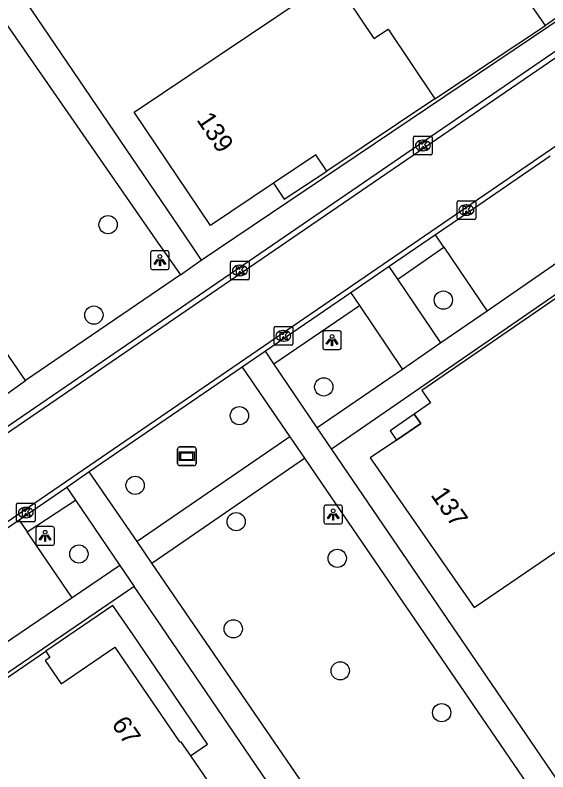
# Model space of a CAD drawing. Extents: x 155275 to 156263, y 382654 to 383635.
# Drawn here: x 155477.14 to 155505.69, y 383303.66 to 383344.2 of the extents above; entities that cross this region are included whole.
import ezdxf

# ---------------------------------------------------------------- set-up
doc = ezdxf.new("R2010")
doc.units = 0
for name, color, linetype in [('IMGEO_Boom', 7, 'Continuous'), ('IMGEO_Kolk', 7, 'Continuous'), ('IMGEO_Lichtpunt', 7, 'Continuous'), ('IMGEO_Muur', 7, 'Continuous'), ('IMGEO_Pand', 7, 'Continuous'), ('IMGEO_Pand_nummerreeks', 7, 'Continuous'), ('IMGEO_Pand_overbouw', 7, 'Continuous'), ('IMGEO_Parkeervlak_open', 7, 'Continuous'), ('IMGEO_Rijbaan_lokaal_open', 7, 'Continuous'), ('IMGEO_Straatnaambord', 7, 'Continuous'), ('IMGEO_Voetpad_open', 7, 'Continuous')]:
    doc.layers.add(name, color=color, linetype=linetype)

msp = doc.modelspace()

# ---------------------------------------------------------------- linework, layer by layer
at = {"layer": 'IMGEO_Boom'}
for centre in [(155482.122, 383332.97), (155500.085, 383328.932), (155481.36, 383328.128), (155493.679, 383324.283), (155489.159, 383322.742), (155483.57, 383319.01), (155488.986, 383317.065), (155480.556, 383315.331), (155494.4, 383315.099), (155488.828, 383311.321), (155494.56, 383309.073), (155499.993, 383306.834)]:
    msp.add_circle(centre, 0.489, dxfattribs=at)
at = {"layer": 'IMGEO_Kolk'}
for p, q in [((155498.488, 383336.787), (155498.488, 383337.639)), ((155498.563, 383337.713), (155499.415, 383337.713)), ((155498.976, 383337.493), (155499.001, 383337.493)), ((155499.489, 383337.639), (155499.489, 383336.787)), ((155498.999, 383336.933), (155498.974, 383336.933)), ((155499.415, 383336.713), (155498.563, 383336.713)), ((155500.824, 383333.33), (155500.824, 383334.182)), ((155500.899, 383334.256), (155501.751, 383334.256)), ((155501.825, 383334.182), (155501.825, 383333.33)), ((155501.312, 383334.036), (155501.337, 383334.036)), ((155501.335, 383333.476), (155501.31, 383333.476)), ((155501.751, 383333.256), (155500.899, 383333.256)), ((155488.681, 383330.094), (155488.681, 383330.946)), ((155488.756, 383331.02), (155489.608, 383331.02)), ((155489.682, 383330.946), (155489.682, 383330.094)), ((155489.169, 383330.8), (155489.194, 383330.8)), ((155489.192, 383330.24), (155489.167, 383330.24)), ((155489.608, 383330.02), (155488.756, 383330.02)), ((155491.015, 383326.593), (155491.015, 383327.445)), ((155491.09, 383327.519), (155491.942, 383327.519)), ((155491.503, 383327.299), (155491.528, 383327.299)), ((155492.016, 383327.445), (155492.016, 383326.593)), ((155491.942, 383326.519), (155491.09, 383326.519)), ((155491.526, 383326.739), (155491.501, 383326.739)), ((155477.213, 383317.123), (155477.213, 383317.975)), ((155477.288, 383318.049), (155478.14, 383318.049)), ((155478.214, 383317.975), (155478.214, 383317.123)), ((155477.701, 383317.829), (155477.726, 383317.829)), ((155477.724, 383317.269), (155477.699, 383317.269)), ((155478.14, 383317.049), (155477.288, 383317.049))]:
    msp.add_line(p, q, dxfattribs=at)
for points in [[(155498.488, 383336.787), (155498.488, 383337.639)], [(155498.563, 383337.713), (155499.415, 383337.713)], [(155498.809, 383337.413), (155498.932, 383337.413), (155498.932, 383337.262), (155499.062, 383337.413), (155499.226, 383337.413), (155499.08, 383337.262), (155499.233, 383337.013), (155499.081, 383337.013), (155498.996, 383337.177), (155498.932, 383337.11), (155498.932, 383337.013), (155498.809, 383337.013), (155498.809, 383337.413)], [(155499.489, 383337.639), (155499.489, 383336.787)], [(155499.415, 383336.713), (155498.563, 383336.713)], [(155500.824, 383333.33), (155500.824, 383334.182)], [(155500.899, 383334.256), (155501.751, 383334.256)], [(155501.825, 383334.182), (155501.825, 383333.33)], [(155501.145, 383333.956), (155501.268, 383333.956), (155501.268, 383333.805), (155501.398, 383333.956), (155501.562, 383333.956), (155501.416, 383333.805), (155501.569, 383333.556), (155501.417, 383333.556), (155501.332, 383333.72), (155501.268, 383333.653), (155501.268, 383333.556), (155501.145, 383333.556), (155501.145, 383333.956)], [(155501.751, 383333.256), (155500.899, 383333.256)], [(155488.681, 383330.094), (155488.681, 383330.946)], [(155488.756, 383331.02), (155489.608, 383331.02)], [(155489.682, 383330.946), (155489.682, 383330.094)], [(155489.002, 383330.72), (155489.125, 383330.72), (155489.125, 383330.569), (155489.255, 383330.72), (155489.419, 383330.72), (155489.273, 383330.569), (155489.426, 383330.32), (155489.274, 383330.32), (155489.189, 383330.484), (155489.125, 383330.417), (155489.125, 383330.32), (155489.002, 383330.32), (155489.002, 383330.72)], [(155489.608, 383330.02), (155488.756, 383330.02)], [(155491.015, 383326.593), (155491.015, 383327.445)], [(155491.09, 383327.519), (155491.942, 383327.519)], [(155491.336, 383327.219), (155491.459, 383327.219), (155491.459, 383327.068), (155491.589, 383327.219), (155491.753, 383327.219), (155491.607, 383327.068), (155491.76, 383326.819), (155491.608, 383326.819), (155491.523, 383326.983), (155491.459, 383326.916), (155491.459, 383326.819), (155491.336, 383326.819), (155491.336, 383327.219)], [(155492.016, 383327.445), (155492.016, 383326.593)], [(155491.942, 383326.519), (155491.09, 383326.519)], [(155477.213, 383317.123), (155477.213, 383317.975)], [(155477.288, 383318.049), (155478.14, 383318.049)], [(155478.214, 383317.975), (155478.214, 383317.123)], [(155477.534, 383317.749), (155477.657, 383317.749), (155477.657, 383317.598), (155477.787, 383317.749), (155477.951, 383317.749), (155477.805, 383317.598), (155477.958, 383317.349), (155477.806, 383317.349), (155477.721, 383317.513), (155477.657, 383317.446), (155477.657, 383317.349), (155477.534, 383317.349), (155477.534, 383317.749)], [(155478.14, 383317.049), (155477.288, 383317.049)]]:
    msp.add_lwpolyline(points, dxfattribs=at)
for centre, start, end in [((155498.565, 383337.637), 91.552, 178.448), ((155498.565, 383337.637), 91.552, 178.448), ((155499.413, 383337.637), 1.552, 88.448), ((155499.413, 383337.637), 1.552, 88.448), ((155498.565, 383336.789), 181.552, 268.448), ((155498.565, 383336.789), 181.552, 268.448), ((155499.413, 383336.789), 271.552, 358.448), ((155499.413, 383336.789), 271.552, 358.448), ((155500.901, 383334.18), 91.552, 178.448), ((155500.901, 383334.18), 91.552, 178.448), ((155501.749, 383334.18), 1.552, 88.448), ((155501.749, 383334.18), 1.552, 88.448), ((155500.901, 383333.332), 181.552, 268.448), ((155500.901, 383333.332), 181.552, 268.448), ((155501.749, 383333.332), 271.552, 358.448), ((155501.749, 383333.332), 271.552, 358.448), ((155488.758, 383330.944), 91.552, 178.448), ((155488.758, 383330.944), 91.552, 178.448), ((155489.606, 383330.944), 1.552, 88.448), ((155489.606, 383330.944), 1.552, 88.448), ((155488.758, 383330.096), 181.552, 268.448), ((155488.758, 383330.096), 181.552, 268.448), ((155489.606, 383330.096), 271.552, 358.448), ((155489.606, 383330.096), 271.552, 358.448), ((155491.092, 383327.443), 91.552, 178.448), ((155491.092, 383327.443), 91.552, 178.448), ((155491.94, 383327.443), 1.552, 88.448), ((155491.94, 383327.443), 1.552, 88.448), ((155491.092, 383326.595), 181.552, 268.448), ((155491.092, 383326.595), 181.552, 268.448), ((155491.94, 383326.595), 271.552, 358.448), ((155491.94, 383326.595), 271.552, 358.448), ((155477.29, 383317.973), 91.552, 178.448), ((155477.29, 383317.973), 91.552, 178.448), ((155478.138, 383317.973), 1.552, 88.448), ((155478.138, 383317.973), 1.552, 88.448), ((155477.29, 383317.125), 181.552, 268.448), ((155477.29, 383317.125), 181.552, 268.448), ((155478.138, 383317.125), 271.552, 358.448), ((155478.138, 383317.125), 271.552, 358.448)]:
    msp.add_arc(centre, 0.0765, start, end, dxfattribs=at)
for centre, major_axis, ratio, start_param, end_param in [((155498.975, 383337.213), (-0.387, 0.002), 0.722429, 4.712389, 7.853982), ((155499, 383337.213), (-0.39, 0.002), 0.717154, 1.570796, 4.712389), ((155501.311, 383333.756), (-0.387, 0.002), 0.722429, 4.712389, 7.853982), ((155501.336, 383333.756), (-0.39, 0.002), 0.717154, 1.570796, 4.712389), ((155489.168, 383330.52), (-0.387, 0.002), 0.722429, 4.712389, 7.853982), ((155489.193, 383330.52), (-0.39, 0.002), 0.717154, 1.570796, 4.712389), ((155491.502, 383327.019), (-0.387, 0.002), 0.722429, 4.712389, 7.853982), ((155491.527, 383327.019), (-0.39, 0.002), 0.717154, 1.570796, 4.712389), ((155477.7, 383317.549), (-0.387, 0.002), 0.722429, 4.712389, 7.853982), ((155477.725, 383317.549), (-0.39, 0.002), 0.717154, 1.570796, 4.712389)]:
    msp.add_ellipse(centre, major_axis=major_axis, ratio=ratio, start_param=start_param, end_param=end_param, dxfattribs=at)
at = {"layer": 'IMGEO_Lichtpunt'}
for p, q in [((155484.398, 383331.469), (155484.398, 383330.662)), ((155484.398, 383331.469), (155484.398, 383330.662)), ((155485.3, 383331.564), (155484.492, 383331.564)), ((155485.3, 383331.564), (155484.492, 383331.564)), ((155485.394, 383330.662), (155485.394, 383331.469)), ((155485.394, 383330.662), (155485.394, 383331.469)), ((155484.492, 383330.568), (155485.3, 383330.568)), ((155484.492, 383330.568), (155485.3, 383330.568)), ((155494.525, 383327.284), (155493.717, 383327.284)), ((155494.525, 383327.284), (155493.717, 383327.284)), ((155493.623, 383327.189), (155493.623, 383326.382)), ((155493.623, 383327.189), (155493.623, 383326.382)), ((155494.619, 383326.382), (155494.619, 383327.189)), ((155494.619, 383326.382), (155494.619, 383327.189)), ((155493.717, 383326.288), (155494.525, 383326.288)), ((155493.717, 383326.288), (155494.525, 383326.288)), ((155494.587, 383317.94), (155493.779, 383317.94)), ((155494.587, 383317.94), (155493.779, 383317.94)), ((155493.685, 383317.845), (155493.685, 383317.038)), ((155493.685, 383317.845), (155493.685, 383317.038)), ((155494.681, 383317.038), (155494.681, 383317.845)), ((155494.681, 383317.038), (155494.681, 383317.845)), ((155478.249, 383316.7), (155478.249, 383315.893)), ((155478.249, 383316.7), (155478.249, 383315.893)), ((155479.151, 383316.795), (155478.343, 383316.795)), ((155479.151, 383316.795), (155478.343, 383316.795)), ((155479.245, 383315.893), (155479.245, 383316.7)), ((155479.245, 383315.893), (155479.245, 383316.7)), ((155493.779, 383316.944), (155494.587, 383316.944)), ((155493.779, 383316.944), (155494.587, 383316.944)), ((155478.343, 383315.799), (155479.151, 383315.799)), ((155478.343, 383315.799), (155479.151, 383315.799))]:
    msp.add_line(p, q, dxfattribs=at)
for points in [[(155484.772, 383331.133), (155484.811, 383331.105), (155484.623, 383330.843), (155484.585, 383330.87), (155484.772, 383331.133)], [(155484.874, 383331.085), (155484.921, 383331.085), (155484.921, 383330.763), (155484.874, 383330.763), (155484.874, 383331.085)], [(155484.984, 383331.105), (155485.022, 383331.132), (155485.209, 383330.87), (155485.17, 383330.842), (155484.984, 383331.105)], [(155493.997, 383326.853), (155494.036, 383326.825), (155493.848, 383326.563), (155493.81, 383326.59), (155493.997, 383326.853)], [(155494.099, 383326.805), (155494.146, 383326.805), (155494.146, 383326.483), (155494.099, 383326.483), (155494.099, 383326.805)], [(155494.209, 383326.825), (155494.247, 383326.852), (155494.434, 383326.59), (155494.395, 383326.562), (155494.209, 383326.825)], [(155494.059, 383317.509), (155494.098, 383317.481), (155493.91, 383317.219), (155493.872, 383317.246), (155494.059, 383317.509)], [(155494.271, 383317.481), (155494.309, 383317.508), (155494.496, 383317.246), (155494.457, 383317.218), (155494.271, 383317.481)], [(155494.161, 383317.461), (155494.208, 383317.461), (155494.208, 383317.139), (155494.161, 383317.139), (155494.161, 383317.461)], [(155478.623, 383316.364), (155478.662, 383316.336), (155478.474, 383316.074), (155478.436, 383316.101), (155478.623, 383316.364)], [(155478.725, 383316.316), (155478.772, 383316.316), (155478.772, 383315.994), (155478.725, 383315.994), (155478.725, 383316.316)], [(155478.835, 383316.336), (155478.873, 383316.363), (155479.06, 383316.101), (155479.021, 383316.073), (155478.835, 383316.336)]]:
    msp.add_lwpolyline(points, dxfattribs=at)
for centre in [(155484.897, 383331.267), (155494.122, 383326.987), (155494.184, 383317.643), (155478.748, 383316.498)]:
    msp.add_circle(centre, 0.0994, dxfattribs=at)
for centre, start, end in [((155484.492, 383331.469), 90, 180), ((155484.492, 383331.469), 90, 180), ((155485.3, 383331.469), 0, 90), ((155485.3, 383331.469), 0, 90), ((155484.492, 383330.662), 180, 270), ((155484.492, 383330.662), 180, 270), ((155485.3, 383330.662), 270, 0), ((155485.3, 383330.662), 270, 360), ((155493.717, 383327.189), 90, 180), ((155493.717, 383327.189), 90, 180), ((155494.525, 383327.189), 0, 90), ((155494.525, 383327.189), 0, 90), ((155493.717, 383326.382), 180, 270), ((155493.717, 383326.382), 180, 270), ((155494.525, 383326.382), 270, 0), ((155494.525, 383326.382), 270, 360), ((155493.779, 383317.845), 90, 180), ((155493.779, 383317.845), 90, 180), ((155494.587, 383317.845), 0, 90), ((155494.587, 383317.845), 0, 90), ((155478.343, 383316.7), 90, 180), ((155478.343, 383316.7), 90, 180), ((155479.151, 383316.7), 0, 90), ((155479.151, 383316.7), 0, 90), ((155493.779, 383317.038), 180, 270), ((155493.779, 383317.038), 180, 270), ((155494.587, 383317.038), 270, 0), ((155494.587, 383317.038), 270, 360), ((155478.343, 383315.893), 180, 270), ((155478.343, 383315.893), 180, 270), ((155479.151, 383315.893), 270, 0), ((155479.151, 383315.893), 270, 360)]:
    msp.add_arc(centre, 0.0946, start, end, dxfattribs=at)
at = {"layer": 'IMGEO_Muur'}
msp.add_lwpolyline([(155499.623, 383339.712), (155505.556, 383343.643)], dxfattribs=at)
at = {"layer": 'IMGEO_Pand'}
for points in [[(155507.508, 383345.001), (155507.473, 383344.976), (155505.556, 383343.643), (155503.094, 383347.184), (155506.697, 383349.656), (155508.02, 383347.727)], [(155499.623, 383339.712), (155493.84, 383335.845), (155493.247, 383336.716), (155490.985, 383335.2), (155487.602, 383332.925), (155483.522, 383339.002), (155494.198, 383346.171), (155496.364, 383342.946), (155497.122, 383343.453), (155499.623, 383339.712)], [(155506.616, 383323.409), (155508.618, 383324.814), (155508.705, 383324.685), (155508.725, 383324.698), (155513.905, 383328.28), (155511.279, 383331.885), (155511.756, 383332.221), (155511.436, 383332.677), (155498.932, 383324.092), (155499.392, 383323.423), (155498.526, 383322.828), (155498.877, 383322.318), (155497.576, 383321.425), (155496.169, 383320.475), (155501.73, 383312.467), (155510.335, 383318.33), (155509.794, 383319.11), (155509.947, 383319.214), (155509.748, 383319.519), (155509.469, 383319.337), (155506.616, 383323.409)], [(155479.026, 383295.337), (155478.746, 383295.745), (155479.257, 383296.096), (155472.866, 383305.465), (155472.33, 383305.097), (155472.047, 383305.51), (155478.777, 383310.12), (155478.999, 383309.792), (155478.75, 383309.624), (155479.613, 383308.378), (155482.489, 383310.333), (155485.946, 383305.261), (155485.996, 383305.295), (155486.531, 383304.516), (155488.193, 383302.091), (155489.109, 383302.716), (155489.333, 383302.394), (155479.026, 383295.337)]]:
    msp.add_lwpolyline(points, dxfattribs=at)
at = {"layer": 'IMGEO_Pand_overbouw'}
for points in [[(155493.84, 383335.845), (155493.247, 383336.716), (155490.985, 383335.2), (155491.564, 383334.34)], [(155498.526, 383322.828), (155497.229, 383321.935), (155497.576, 383321.425), (155498.877, 383322.318)], [(155478.777, 383310.12), (155478.999, 383309.792), (155478.75, 383309.624), (155479.613, 383308.378), (155482.489, 383310.333), (155485.946, 383305.261), (155485.996, 383305.295), (155486.531, 383304.516), (155487.452, 383305.144), (155483.46, 383310.993), (155482.383, 383312.571)]]:
    msp.add_lwpolyline(points, close=True, dxfattribs=at)
at = {"layer": 'IMGEO_Parkeervlak_open'}
for points in [[(155500.119, 383331.762), (155502.437, 383328.348)], [(155499.948, 383326.646), (155497.645, 383330.046)], [(155495.59, 383328.646), (155497.895, 383325.214)], [(155480.188, 383312.991), (155477.788, 383316.511)]]:
    msp.add_lwpolyline(points, dxfattribs=at)
at = {"layer": 'IMGEO_Rijbaan_lokaal_open'}
for points in [[(155545.973, 383369.225), (155512.791, 383346.508), (155450.858, 383304.106), (155413.779, 383278.713), (155415.989, 383275.504), (155453.502, 383301.158), (155500.38, 383333.268), (155548.143, 383365.998)], [(155449.748, 383303.711), (155450.724, 383304.38), (155450.774, 383304.414), (155508.223, 383343.736)], [(155505.817, 383336.646), (155500.559, 383333.044), (155499.665, 383332.432)], [(155499.665, 383332.432), (155497.181, 383330.731)], [(155497.181, 383330.731), (155495.133, 383329.328)], [(155495.133, 383329.328), (155490.548, 383326.188)], [(155490.548, 383326.188), (155489.301, 383325.333)], [(155489.301, 383325.333), (155481.111, 383319.724)], [(155481.111, 383319.724), (155479.909, 383318.901)], [(155479.909, 383318.901), (155477.352, 383317.15)], [(155477.352, 383317.15), (155473.267, 383314.353)]]:
    msp.add_lwpolyline(points, dxfattribs=at)
at = {"layer": 'IMGEO_Straatnaambord'}
for p, q in [((155485.844, 383320.168), (155485.844, 383320.968)), ((155485.844, 383320.968), (155485.844, 383320.168)), ((155485.944, 383321.068), (155486.734, 383321.068)), ((155486.734, 383321.068), (155485.944, 383321.068)), ((155486.834, 383320.968), (155486.834, 383320.168)), ((155486.834, 383320.168), (155486.834, 383320.968)), ((155486.734, 383320.068), (155485.944, 383320.068)), ((155485.944, 383320.068), (155486.734, 383320.068))]:
    msp.add_line(p, q, dxfattribs=at)
for points in [[(155485.945, 383320.8), (155486.733, 383320.8), (155486.733, 383320.336), (155485.945, 383320.336), (155485.945, 383320.8)], [(155486.01, 383320.735), (155486.01, 383320.401), (155486.668, 383320.401), (155486.668, 383320.735), (155486.01, 383320.735)]]:
    msp.add_lwpolyline(points, dxfattribs=at)
for centre, start, end in [((155485.944, 383320.968), 90, 180), ((155485.944, 383320.968), 90, 180), ((155486.734, 383320.968), 0, 90), ((155486.734, 383320.968), 360, 90), ((155485.944, 383320.168), 180, 270), ((155485.944, 383320.168), 180, 270), ((155486.734, 383320.168), 270, 0), ((155486.734, 383320.168), 270, 0)]:
    msp.add_arc(centre, 0.1, start, end, dxfattribs=at)
at = {"layer": 'IMGEO_Voetpad_open'}
for points in [[(155439.322, 383401.258), (155440.503, 383399.413), (155458.765, 383372.788), (155486.531, 383331.928), (155487.116, 383331.079)], [(155477.689, 383324.618), (155476.367, 383326.551), (155460.597, 383349.744), (155468.656, 383355.272), (155471.97, 383350.495), (155484.687, 383332.167), (155486.004, 383330.281)], [(155487.116, 383331.079), (155507.596, 383344.851)], [(155494.094, 383320.967), (155516.069, 383336.112)], [(155508.581, 383332.595), (155502.437, 383328.348)], [(155500.119, 383331.762), (155499.665, 383332.432)], [(155497.645, 383330.046), (155500.119, 383331.762)], [(155486.004, 383330.281), (155487.116, 383331.079)], [(155497.645, 383330.046), (155497.181, 383330.731)], [(155486.004, 383330.281), (155477.689, 383324.618)], [(155495.133, 383329.328), (155495.59, 383328.646)], [(155491.008, 383325.509), (155495.59, 383328.646)], [(155502.437, 383328.348), (155499.948, 383326.646)], [(155499.948, 383326.646), (155497.895, 383325.214)], [(155491.008, 383325.509), (155490.548, 383326.188)], [(155489.301, 383325.333), (155491.858, 383321.607)], [(155493.321, 383322.096), (155491.008, 383325.509)], [(155497.895, 383325.214), (155493.321, 383322.096)], [(155476.546, 383323.803), (155477.689, 383324.618)], [(155494.094, 383320.967), (155493.321, 383322.096)], [(155491.858, 383321.607), (155483.675, 383315.993)], [(155491.858, 383321.607), (155492.642, 383320.466)], [(155558.036, 383227.48), (155509.565, 383298.295), (155495.01, 383319.623), (155494.094, 383320.967)], [(155492.642, 383320.466), (155493.56, 383319.128), (155505.52, 383301.627), (155497.352, 383296.056), (155485.867, 383312.804), (155484.464, 383314.845)], [(155484.464, 383314.845), (155492.642, 383320.466)], [(155483.675, 383315.993), (155481.111, 383319.724)], [(155479.909, 383318.901), (155480.371, 383318.222)], [(155477.788, 383316.511), (155480.371, 383318.222)], [(155480.371, 383318.222), (155482.752, 383314.722)], [(155477.352, 383317.15), (155477.788, 383316.511)], [(155484.464, 383314.845), (155483.675, 383315.993)], [(155482.752, 383314.722), (155480.188, 383312.991)], [(155482.752, 383314.722), (155483.519, 383313.595)], [(155483.519, 383313.595), (155458.608, 383296.58), (155454.563, 383293.76)], [(155547.42, 383220.262), (155498.922, 383291.025), (155490.365, 383303.561), (155484.692, 383311.871), (155483.519, 383313.595)], [(155480.188, 383312.991), (155476.098, 383310.206)]]:
    msp.add_lwpolyline(points, dxfattribs=at)

# ---------------------------------------------------------------- texts
at = {"layer": 'IMGEO_Pand_nummerreeks'}
for s, rotation, p in [('139', 303.8829, (155486.837, 383338.585)), ('137', 304.5778, (155499.378, 383318.492)), ('67', 304.2799, (155482.273, 383306.21))]:
    msp.add_text(s, height=1, rotation=rotation, dxfattribs=at).set_placement(p)

doc.saveas('drawing.dxf')
